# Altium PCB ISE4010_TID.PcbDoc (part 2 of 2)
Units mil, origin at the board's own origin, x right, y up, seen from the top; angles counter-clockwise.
Board outline 9000 x 8000 mil, 4 copper layers (Layer 1 - Top Layer, Layer 2 - GND, Layer 3 - PWR, Layer 4 - Bottom Layer), stack 65.6 mil thick; 159 components, 101 nets, 426 pads, 332 vias.
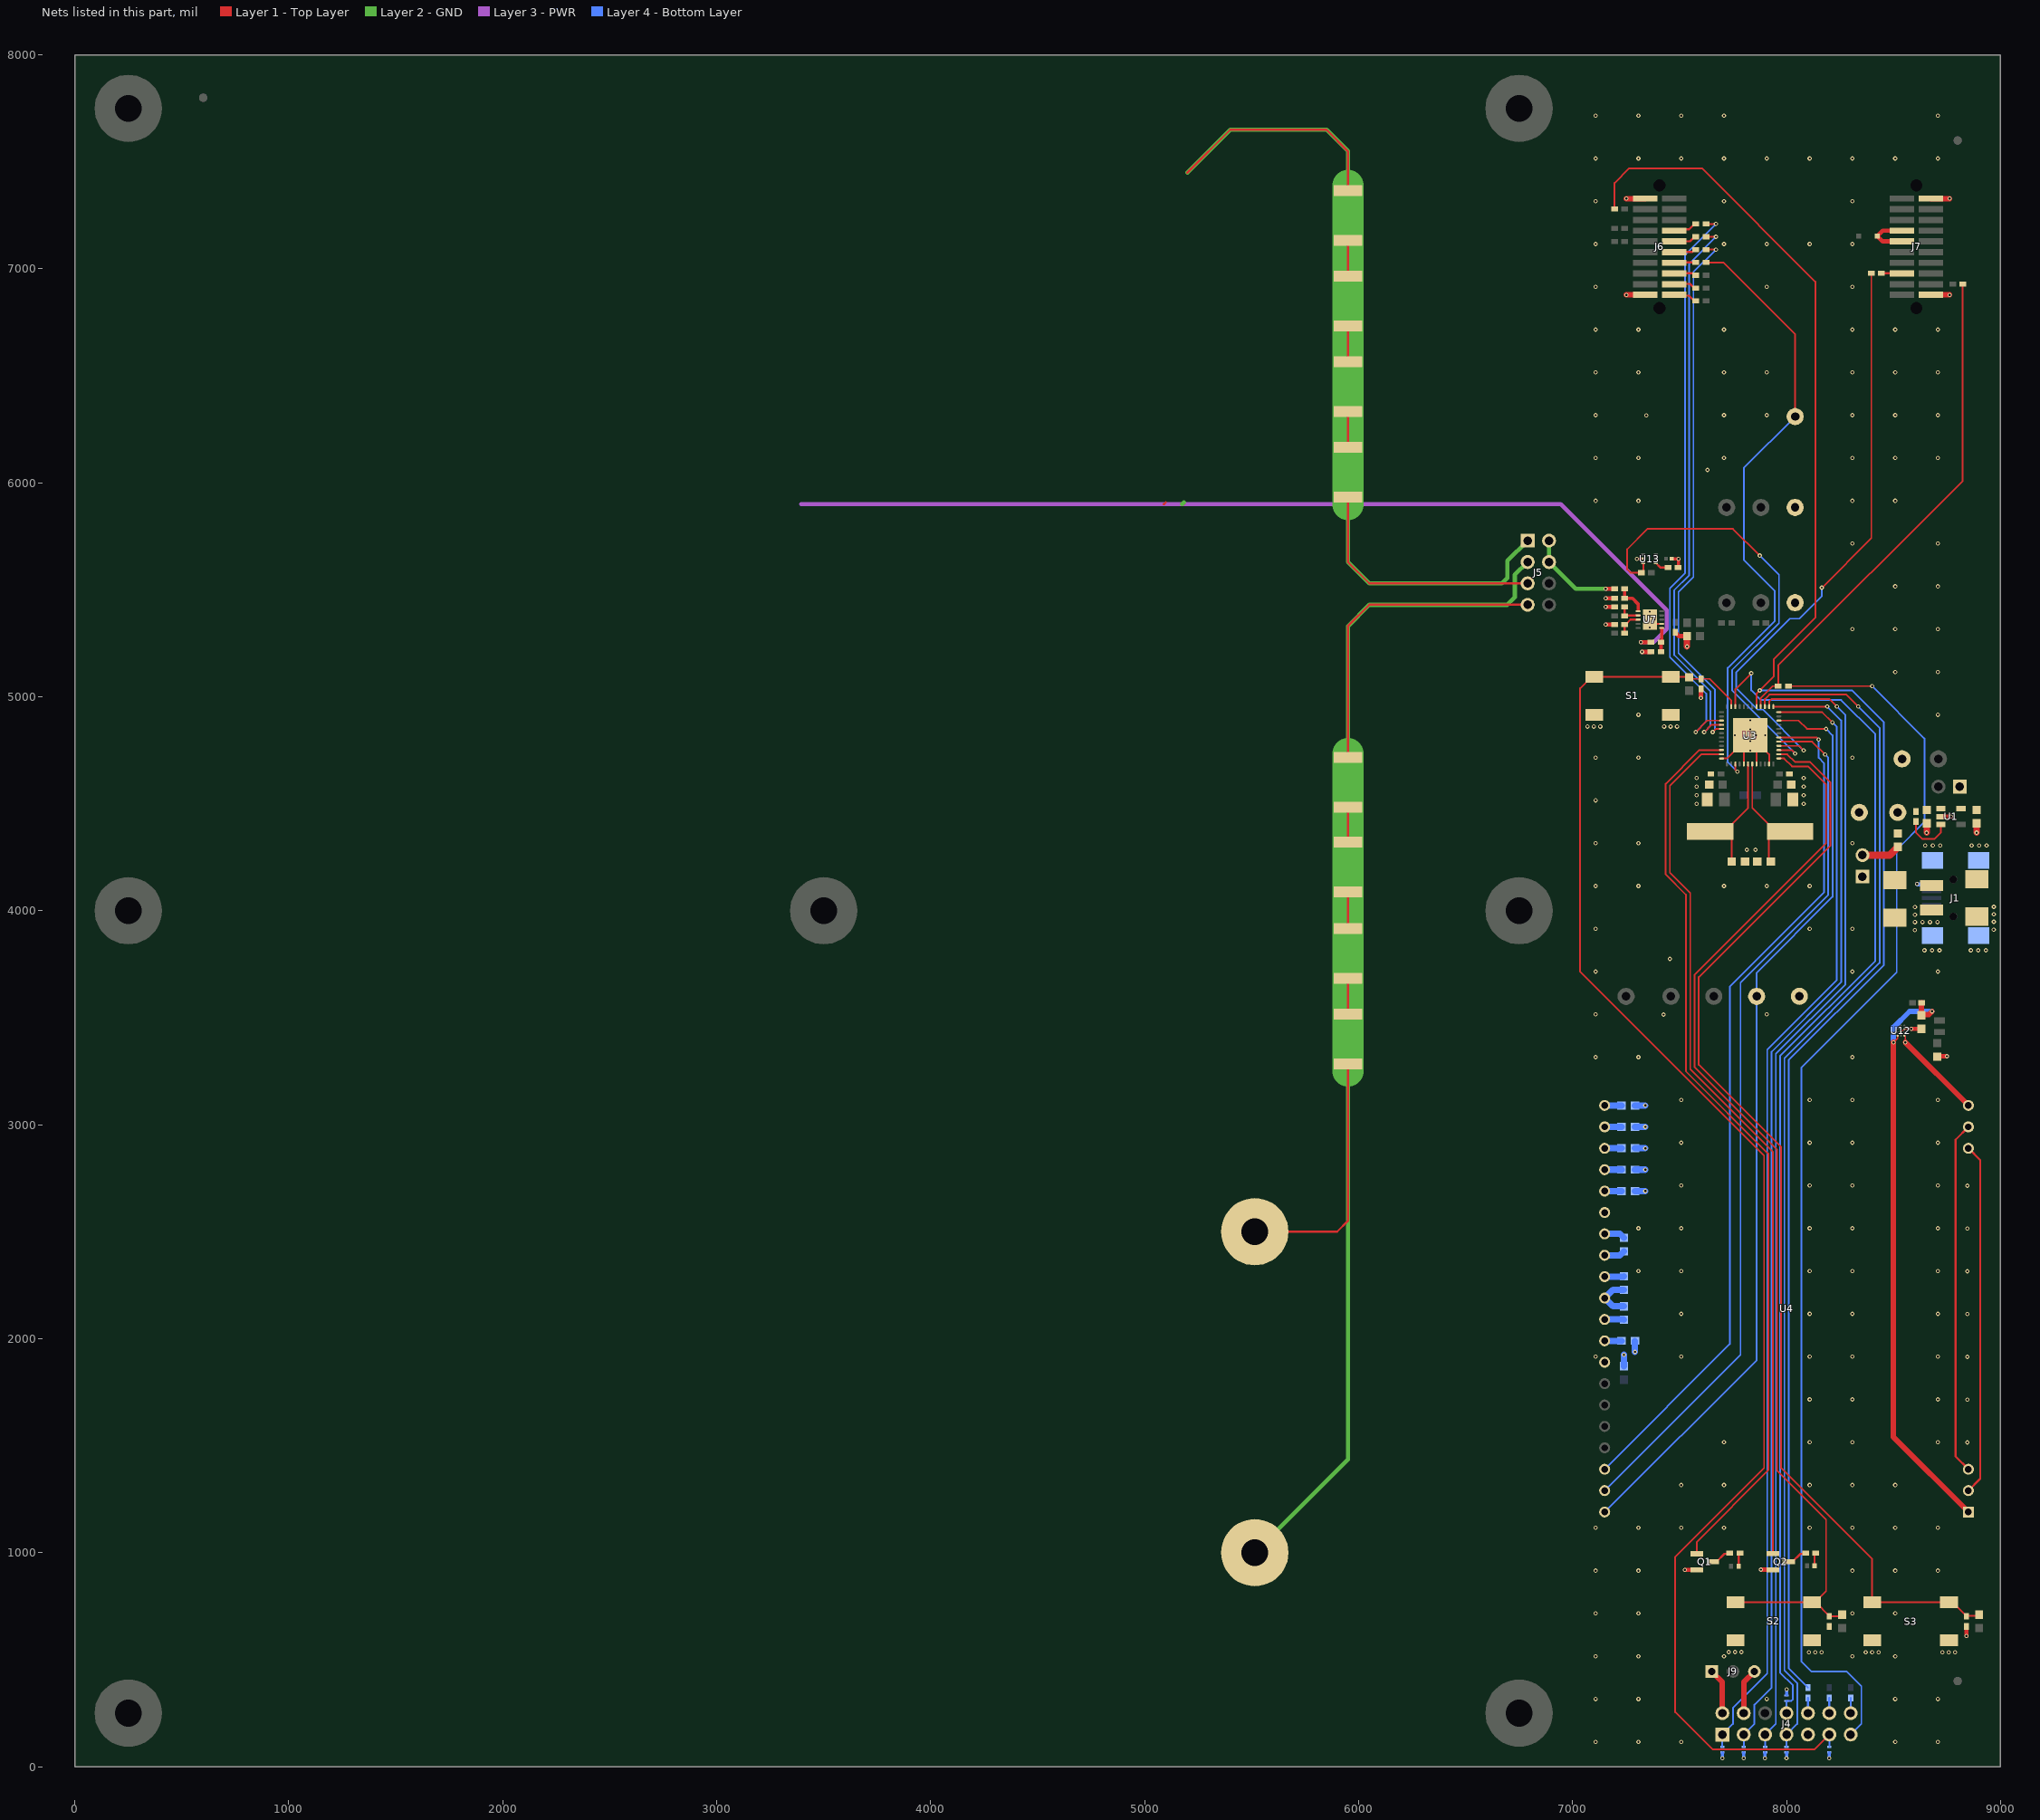
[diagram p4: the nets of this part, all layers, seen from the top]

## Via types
v1: diameter 20, hole 10, Layer 1 - Top Layer to Layer 4 - Bottom Layer, 320 vias
v2: diameter 19.68, hole 7.87, Layer 1 - Top Layer to Layer 4 - Bottom Layer, 12 vias

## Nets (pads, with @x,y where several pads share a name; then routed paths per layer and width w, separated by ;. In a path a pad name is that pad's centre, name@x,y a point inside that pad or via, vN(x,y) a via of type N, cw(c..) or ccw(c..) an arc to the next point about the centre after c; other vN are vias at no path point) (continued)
GND: C1.1 C2.2 C3.2 C4.1 C5.2 C6.2 C7.2 C9.1 C10.2 C11.1 C14.1 C15.2 C16.1 C17.2 C18.2 C19.2 C20.2 C21.2 C22.2 C23.2 C24.2 C25.2 C26.2 C27.1 C28.2 C29.1 C30.1 C34.2 C35.2 C36.2 D1.2 D6.1 J1.5 J1.6 J1.7 J1.8 J1.9 J4.9 J6.2 J6.20 J7.1 J7.19 Q1.2 Q2.2 R25.2 S1.3 S1.4 S2.3 S2.4 S3.3 S3.4 TP2.1 TP13.1 TP14.1 TP15.1 TP16.1 U1.2 U3.36 U3.41 U3.44 U3.47 U3.49 U4.26 U4.33 U5.2 U6.2 U7.7 U7.11 U8.2 U9.2 U10.2 U11.2 U12.B3 U12.C2 U13.2 | length 2260.9
  Layer 1 - Top Layer w4: U12.C2@8534.92,3432.05 U12.B3@8550.67,3447.8
  Layer 1 - Top Layer w8: U7.11@7380.82,5341.05 U7.7@7416.25,5341.05 ; U3.36@7696.14,4711.73 7721.73,4711.73 7800.47,4790.47 U3.41@7800.47,4686.14 ; U3.49@7830,4820 U3.49@7859.53,4790.47 ; U3.44@7859.53,4686.14 U3.49@7859.53,4790.47 ; U3.47@7918.58,4686.14 7918.58,4731.42 U3.49@7859.53,4790.47 ; U12.B3@8550.67,3447.8 v1(8582.8,3447.8)
  Layer 1 - Top Layer w10: v1(7300,5645) U13.2@7330.47,5645
  Layer 1 - Top Layer w15: C36.2@7462.99,5645 v1(7495,5645) 7495,5606.38 R25.2@7493.62,5605
  Layer 1 - Top Layer w20: v1(7155,5337.99) C30.1@7196.38,5337.99 ; v1(7155,5420) C29.1@7196.38,5420 ; v1(7155,5460) C2.2@7196.38,5460 ; v1(7325,5210) C3.2@7366.38,5210 ; C27.1@7480,5301.38 7497.87,5283.5 C23.2@7535,5283.5 ; v1(7525,920) Q1.2@7581.02,920 ; v1(7600,4995) C10.2@7600,5036.38 ; v1(7880,920.46) Q2.2@7936.02,920.46 ; v1(8582.8,3447.8) 8629.29,3447.8 C35.2@8629.92,3448.43 ; C34.2@8704.92,3318.43 8706.5,3320 v1(8750,3320) ; U1.2@8721.3,4440 v1(8768.54,4440) ; v1(8840.25,610.25) C17.2@8840.25,655.5
  Layer 1 - Top Layer w25: v1(7251.49,6878.51) J6.2@7339.47,6878.51 ; v1(7251.49,7328.51) J6.20@7339.47,7328.51 ; J7.1@8674.51,6878.51 v1(8762.49,6878.51) ; J7.19@8674.51,7328.51 v1(8762.49,7328.51)
  Layer 1 - Top Layer w30: v1(7535,5235) C23.2@7535,5283.5 ; v1(8655,4365) C1.1@8655,4408.5 ; v1(8888.54,4365) C4.1@8888.54,4408.5
  Layer 4 - Bottom Layer w15: v1@7700,39 U5.2@7700,64 ; v1@7800,39 U8.2@7800,64 ; v1@7900,39 U10.2@7900,64 ; v1@8000,39 U11.2@8000,64 ; U6.2@8000,336 v1@8000,361 ; v1@8200,39 U9.2@8200,64
  Layer 4 - Bottom Layer w30: C18.2@7240,1871.5 v1(7240,1925) ; v1(7291.5,1938.5) C19.2@7291.5,1990 ; C20.2@7291.5,2690 v1(7340,2690) ; C21.2@7291.5,2790 v1(7340,2790) ; C22.2@7291.5,2890 v1(7340,2890) ; C26.2@7291.5,2990 v1(7340,2990) ; C28.2@7291.5,3090 v1(7340,3090)
  other v1: 7699.75,39 7799.75,39 7899.75,39 7999.75,39 8199.75,39 7108,116 7308,116 7508,116 8508,116 8708,116 7108,316 7308,316 7908,316 8508,316 8708,316 8000.25,361 7108,516 7308,516 7708,516 8308,516 8508,516 8103.88,534.46 8133.88,534.46 8163.88,534.46 8370,535 8400,535 8430,535 8728.27,535 8758.27,535 8788.27,535 7729.75,535.88 7759.75,535.88 7789.75,535.88 7108,716 7308,716 8308,716 8508,716 7108,916 7308,916 8308,916 8508,916 8708,916 7108,1116 7308,1116 7508,1116 7708,1116 8108,1116 8308,1116 8508,1116 8708,1116 7508,1316 7708,1316 8108,1316 8308,1316 8508,1316 8845,1515 7708,1516 8108,1516 8308,1516 8708,1516 8845,1715 8108,1716 8308,1716 8708,1716 8845,1915 7108,1916 7508,1916 8108,1916 8308,1916 8708,1916 8845,2115 7508,2116 8108,2116 8308,2116 8708,2116 8845,2315 7308,2316 7508,2316 8108,2316 8308,2316 8708,2316 8845,2515 7308,2516 7508,2516 8108,2516 8308,2516 8708,2516 8845,2715 7508,2716 8108,2716 8308,2716 8708,2716 7508,2916 8108,2916 8308,2916 8708,2916 7508,3116 8108,3116 8308,3116 8708,3116 7108,3316 7308,3316 8308,3316 7425,3515 7108,3516 7908,3516 7108,3716 8308,3716 8708,3716 7455,3775 8644.68,3815 8679.68,3815 8714.68,3815 8861.22,3815 8896.22,3815 8931.22,3815 8600,3910 8968.46,3911.61 7108,3916 8108,3916 8308,3916 8600.2,3946.89 8635.2,3946.89 8670.2,3946.89 8705.2,3946.89 8968.66,3948.5 8600.2,3981.89 8968.66,3983.5 8600.2,4016.89 8968.66,4018.5 7108,4116 7308,4116 7708,4116 7908,4116 8108,4116 7815,4285 7855,4285 8648.46,4305 8683.46,4305 8718.46,4305 8865,4305 8900,4305 8935,4305 7108,4316 7308,4316 8308,4316 7580,4500 8080,4500 7108,4516 7580,4540 8080,4540 7580,4580 8080,4580 7580,4620 8080,4620 7108,4716 7308,4716 8308,4716 7069.75,4860.88 7099.75,4860.88 7129.75,4860.88 7428.02,4860.88 7458.02,4860.88 7488.02,4860.88 7308,4916 8708,4916 8508,5116 8708,5116 8308,5316 8508,5316 8708,5316 8508,5516 8708,5516 8308,5716 8708,5716 7108,5916 7308,5916 8308,5916 8508,5916 7630,6060 7108,6116 7308,6116 7708,6116 8308,6116 8508,6116 8708,6116 7345,6315 7108,6316 7708,6316 7908,6316 8308,6316 8508,6316 8708,6316 7108,6516 7308,6516 7708,6516 7908,6516 8308,6516 8508,6516 8708,6516 7108,6716 7308,6716 7708,6716 8308,6716 8508,6716 8708,6716 7108,6916 7908,6916 8308,6916 7108,7116 7708,7116 7908,7116 8108,7116 8308,7116 7108,7316 7708,7316 8308,7316 7108,7516 7308,7516 7508,7516 7708,7516 7908,7516 8108,7516 8308,7516 8508,7516 8708,7516 7108,7716 7308,7716 7508,7716 7708,7716 8708,7716
  other v2: 7830,4749.13 7830,4792.44 7759.13,4820 7802.44,4820 7857.56,4820 7900.87,4820 7830,4847.56 7830,4890.87 7361.13,5323.33 7338.5,5360.73 7383.77,5360.73 7361.13,5398.13
HFXIN: C25.1 U3.42 Y1.1 | length 583.8
  Layer 1 - Top Layer w8: Y1.1@7642.99,4370 Y1.1@7710,4370 ; Y1.1@7710,4355 Y1.1@7710,4370 ; C25.1@7743.5,4230 Y1.1@7743.5,4370 ; U3.42@7820.16,4686.14 7820.16,4480.16 Y1.1@7710,4370
HFXOUT: C24.1 U3.43 Y1.2 | length 583.8
  Layer 1 - Top Layer w8: U3.43@7839.84,4686.14 7839.84,4480.16 Y1.2@7950,4370 ; C24.1@7916.5,4230 Y1.2@7916.5,4370 ; Y1.2@7950,4355 Y1.2@7950,4370 ; Y1.2@8017.01,4370 Y1.2@7950,4370
ILED: U4.20 U12.D3 | length 450.3
  Layer 1 - Top Layer w8: U12.D3@8550.67,3416.3 8555,3411.97 v1(8555,3385)
  Layer 1 - Top Layer w25: v1(8555,3385) U4.20@8850,3090
LCD_A0: U3.6 U4.38 | length 4035.4
  Layer 1 - Top Layer w8: U3.6@7963.86,4810.16 8139.84,4810.16 v1(8150,4800)
  Layer 4 - Bottom Layer w8: U4.38@7150,1390 7735,1975 7735,3645 8175.16,4085.16 8175.16,4689.84 8150,4715 v1(8150,4800)
LED_1: Q1.1 U3.34 | length 4262.2
  Layer 1 - Top Layer w8: Q1.1@7581.02,994.8 7581.02,1051.02 7915,1385 7915,2865 7530,3250 7530,4075 7435,4170 7435,4593.28 7592.82,4751.1 U3.34@7696.14,4751.1
LED_2: Q2.1 U3.35 | length 4090.8
  Layer 1 - Top Layer w8: U3.35@7696.14,4731.42 7601.42,4731.42 7455,4585 7455,4178.28 7550,4083.28 7550,3260 7936.02,2873.98 Q2.1@7936.02,995.26
LED_CA1: U4.2 U4.18 | length 1646
  Layer 1 - Top Layer w10: U4.2@8850,1290 8905.51,1345.51 8905.51,2834.49 U4.18@8850,2890
LED_CA2: U4.3 U4.19 | length 1649.7
  Layer 1 - Top Layer w10: U4.3@8850,1390 8790,1450 8790,2930 U4.19@8850,2990
NCSB_LCD: TP9.1 U3.10 U4.40 | length 4350.9
  Layer 1 - Top Layer w8: U3.10@7963.86,4888.9 8056.1,4888.9 8095,4850 v1(8185,4850)
  Layer 4 - Bottom Layer w8: U4.40@7150,1190 7860.18,1900.18 TP9.1@7860.18,3599.88 7860.18,3710.18 8215.16,4065.16 8215.16,4819.84 v1(8185,4850)
NCSB_RF: R21.2 TP10.1 U3.39 | length 2909.4
  Layer 1 - Top Layer w8: R21.2@7623.62,7030 7705,7030 8040.18,6694.82 TP10.1@8040.18,6309.89 ; U3.39@7761.1,4686.14 7761.1,4658.9 v1(7770,4650)
  Layer 4 - Bottom Layer w8: v1(7770,4650) 7725,4695 7725,5135 7945,5355 7945,5495 7800,5640 7800,6069.71 TP10.1@8040.18,6309.89
NetC2_1: C2.1 R7.1 U7.1 | length 149.2
  Layer 1 - Top Layer w15: R7.1@7243.62,5505 C2.1@7243.62,5460 7280,5460 7306.02,5433.98 U7.1@7306.02,5403
NetC3_1: C3.1 R30.1 U7.6 | length 109.1
  Layer 1 - Top Layer w15: C3.1@7413.62,5210 R30.1@7413.62,5255 7416.25,5257.63 U7.6@7416.25,5318
NetC4_2: C4.2 J3.1 U1.5
NetC7_1: C7.1 D1.1 D6.2 J1.1 J2.1 | length 68.5
  Layer 4 - Bottom Layer w18: v1(8610,4125) 8612.01,4122.99 J1.1@8677.64,4122.99
NetC19_1: C19.1 U4.32 | length 78.5
  Layer 4 - Bottom Layer w30: U4.32@7150,1990 C19.1@7228.5,1990
NetC20_1: C20.1 U4.25 | length 78.5
  Layer 4 - Bottom Layer w30: U4.25@7150,2690 C20.1@7228.5,2690
NetC21_1: C21.1 U4.24 | length 78.5
  Layer 4 - Bottom Layer w30: U4.24@7150,2790 C21.1@7228.5,2790
NetC22_1: C22.1 U4.23 | length 78.5
  Layer 4 - Bottom Layer w30: U4.23@7150,2890 C22.1@7228.5,2890
NetC26_1: C26.1 U4.22 | length 78.5
  Layer 4 - Bottom Layer w30: U4.22@7150,2990 C26.1@7228.5,2990
NetC28_1: C28.1 U4.21 | length 78.5
  Layer 4 - Bottom Layer w30: U4.21@7150,3090 C28.1@7228.5,3090
NetC29_2: C29.2 R11.2 U7.2 | length 110.4
  Layer 1 - Top Layer w10: C29.2@7243.62,5417.99 R11.2@7243.62,5377.99 7246.05,5380.42 U7.2@7313,5380.42
NetC30_2: C30.2 R12.2 U7.3 | length 118.8
  Layer 1 - Top Layer w10: R12.2@7243.62,5297.99 C30.2@7243.62,5337.99 7248.15,5337.99 7270.89,5360.73 U7.3@7313,5360.73
NetC31_1: C31.1 U4.28 | length 97.7
  Layer 4 - Bottom Layer w30: U4.28@7150,2390 7221.5,2390 C31.1@7240,2408.5
NetC31_2: C31.2 U4.27 | length 97.7
  Layer 4 - Bottom Layer w30: U4.27@7150,2490 7221.5,2490 C31.2@7240,2471.5
NetC32_1: C32.1 U4.31 | length 90.6
  Layer 4 - Bottom Layer w30: U4.31@7150,2090 7238.5,2090 C32.1@7240,2088.5
NetC32_2: C32.2 C33.1 U4.30 | length 211.9
  Layer 4 - Bottom Layer w30: C32.2@7240,2151.5 7188.5,2151.5 U4.30@7150,2190 7188.5,2228.5 C33.1@7240,2228.5
NetC33_2: C33.2 U4.29 | length 90.6
  Layer 4 - Bottom Layer w30: U4.29@7150,2290 7238.5,2290 C33.2@7240,2291.5
NetD2_1: D2.1 R9.2 | length 62.4
  Layer 1 - Top Layer w10: D2.1@7776.14,937.4 7776.14,991.5 R9.2@7782.05,997.4
NetD3_1: D3.1 R10.2 | length 62.4
  Layer 1 - Top Layer w10: D3.1@8131.14,937.86 8131.14,991.95 R10.2@8137.05,997.86
NetD5_1: D5.1 J7.12 J7.14 | length 251
  Layer 1 - Top Layer w20: J7.12@8539.47,7128.51 8448.8,7128.51 D5.1@8424.31,7153 8449.82,7178.51 J7.14@8539.47,7178.51
NetJ4_10: J4.10 R29.2 | length 71.4
  Layer 4 - Bottom Layer w10: J4.10@8100,250 R29.2@8100,321.38
NetJ4_12: J4.12 R28.2 | length 71.4
  Layer 4 - Bottom Layer w10: J4.12@8200,250 R28.2@8200,321.38
NetJ4_13: J4.13 R8.2 | length 5864.4
  Layer 1 - Top Layer w8: R8.2@8008.62,5050 v1(8400,5050)
  Layer 4 - Bottom Layer w8: J4.13@8300,150 8350,200 8350,375 8280,445 8115,445 8070,490 8070,3268 8515,3713 8515,4285 8645,4415 8645,4805 v1(8400,5050)
NetJ4_14: J4.14 R27.2 | length 71.4
  Layer 4 - Bottom Layer w10: J4.14@8300,250 R27.2@8300,321.38
NetJ5_5: J5.5 R34.1 | length 1185.3
  Layer 1 - Top Layer w10: R34.1@5950,5933.86 5950,5630 6050,5530 J5.5@6790,5530
NetJ5_7: J5.7 R31.1 | length 1495.3
  Layer 1 - Top Layer w10: R31.1@5950,4716.14 5950,5330 6050,5430 J5.7@6790,5430
NetJ6_1: J6.1 R17.2 | length 114.9
  Layer 1 - Top Layer w10: J6.1@7475,6880 7480,6875 7544,6875 7570.49,6848.51 R17.2@7576.87,6848.51
NetJ6_3: J6.3 R19.1 | length 110.8
  Layer 1 - Top Layer w10: J6.3@7475,6930 7549,6930 7570.49,6908.51 R19.1@7576.87,6908.51
NetJ6_5: J6.5 R20.1 | length 106.6
  Layer 1 - Top Layer w10: J6.5@7475,6980 7559,6980 7570.49,6968.51 R20.1@7576.87,6968.51
NetJ6_7: J6.7 R21.1 | length 102.5
  Layer 1 - Top Layer w10: J6.7@7474.51,7028.51 7476,7030 R21.1@7576.38,7030
NetJ6_9: J6.9 R18.2 | length 106.6
  Layer 1 - Top Layer w10: J6.9@7474.51,7078.51 7558.51,7078.51 7570,7090 R18.2@7576.38,7090
NetJ6_11: J6.11 R16.2 | length 110.8
  Layer 1 - Top Layer w10: J6.11@7474.51,7128.51 7548.51,7128.51 7570,7150 R16.2@7576.38,7150
NetJ6_13: J6.13 R22.1 | length 114.9
  Layer 1 - Top Layer w10: J6.13@7474.51,7178.51 7481,7185 7545,7185 7570,7210 R22.1@7576.38,7210
NetJ7_6: J7.6 R23.1 | length 96.5
  Layer 1 - Top Layer w10: R23.1@8443.62,6980 8537.98,6980 J7.6@8539.47,6978.51
NetQ1_3: Q1.3 R9.1 | length 95.5
  Layer 1 - Top Layer w10: Q1.3@7655.83,957.4 7672.86,957.4 7710,994.54 7731.95,994.54 R9.1@7734.8,997.4
NetQ2_3: Q2.3 R10.1 | length 95.5
  Layer 1 - Top Layer w10: Q2.3@8010.83,957.86 8027.86,957.86 8065,995 8086.95,995 R10.1@8089.8,997.86
NetR1_1: R1.1 U1.3 | length 229.4
  Layer 1 - Top Layer w8: R1.1@8605,4416.38 8605,4365 8635,4335 8690,4335 8721.3,4366.3 U1.3@8721.3,4402.6
NetR25_1: R25.1 U13.4 | length 65.3
  Layer 1 - Top Layer w10: U13.4@7389.53,5625.31 7409.84,5605 R25.1@7446.38,5605
NetR31_2: R31.2 R35.1 | length 162.7
  Layer 1 - Top Layer w10: R35.1@5950,4321.14 R31.2@5950,4483.86
NetR34_2: R34.2 R38.1 | length 167.7
  Layer 1 - Top Layer w10: R34.2@5950,6166.14 R38.1@5950,6333.86
NetR35_2: R35.2 R39.1 | length 172.7
  Layer 1 - Top Layer w10: R39.1@5950,3916.14 R35.2@5950,4088.86
NetR38_2: R38.2 R42.1 | length 167.7
  Layer 1 - Top Layer w10: R38.2@5950,6566.14 R42.1@5950,6733.86
NetR39_2: R39.2 R43.1 | length 167.7
  Layer 1 - Top Layer w10: R43.1@5950,3516.14 R39.2@5950,3683.86
NetR42_2: R42.2 R46.1 | length 167.7
  Layer 1 - Top Layer w10: R42.2@5950,6966.14 R46.1@5950,7133.86
NRST: C10.1 J4.11 R4.1 S1.1 S1.2 U3.23 U9.1 | length 6995.7
  Layer 1 - Top Layer w8: U3.23@7741.42,4953.86 7741.42,4983.58 7641.38,5083.62 C10.1@7600,5083.62 7552.87,5083.62 R4.1@7545,5091.5 7542.92,5093.58 S1.2@7459.14,5093.58 S1.1@7100.87,5093.58 7088.58,5093.58 7035,5040 7035,3715 7895,2855 7895,1395 7480,980 7480,255 7655,80 8130,80 J4.11@8200,150
  Layer 4 - Bottom Layer w8: U9.1@8200,92.8 J4.11@8200,150
NRST_EM: R23.2 U3.4 | length 2787.8
  Layer 1 - Top Layer w8: U3.4@7963.86,4770.79 8059.21,4770.79 v1(8080,4750) ; v1(8165,5510) 8396.38,5741.38 R23.2@8396.38,6980
  Layer 4 - Bottom Layer w8: v1(8080,4750) 7890,4940 7865,4940 7765,5040 7765,5115 8015,5365 8060,5365 8165,5470 v1(8165,5510)
NRST_LCD: U3.5 U4.39 | length 4120.4
  Layer 1 - Top Layer w8: U3.5@7963.86,4790.47 8119.53,4790.47 v1(8180,4730)
  Layer 4 - Bottom Layer w8: U4.39@7150,1290 7785,1925 7785,3665 8195.16,4075.16 8195.16,4714.84 v1(8180,4730)
OVP: C35.1 D4.1 U4.1 U12.D1 | length 2777.2
  Layer 1 - Top Layer w8: v1(8499.92,3384.92) 8519.17,3404.17 U12.D1@8519.17,3416.3
  Layer 1 - Top Layer w25: v1(8499.92,3384.92) 8499.92,1540.08 U4.1@8850,1190 ; D4.1@8631.57,3569.92 8629.92,3568.27 C35.1@8629.92,3511.42 8633.5,3515 8665,3515 v1(8679.92,3529.92)
  Layer 4 - Bottom Layer w25: v1(8499.92,3384.92) 8499.92,3454.92 8574.92,3529.92 v1(8679.92,3529.92)
P3.4: R22.2 U3.27 | length 2745
  Layer 1 - Top Layer w8: v1(7575,4835) 7628.9,4888.9 U3.27@7696.14,4888.9 ; R22.2@7623.62,7210 v1(7670,7210)
  Layer 4 - Bottom Layer w8: v1(7575,4835) 7625,4885 7625,5015 7455,5185 7455,5506.57 7525,5576.57 7525,7065 v1(7670,7210)
P3.5: R16.1 U3.28 | length 2620.3
  Layer 1 - Top Layer w8: v1(7615,4835) 7649.21,4869.21 U3.28@7696.14,4869.21 ; R16.1@7623.62,7150 v1(7670,7150)
  Layer 4 - Bottom Layer w8: v1(7615,4835) 7645,4865 7645,5025 7475,5195 7475,5498.28 7545,5568.28 7545,7025 v1(7670,7150)
P3.6: R18.1 U3.29 | length 2495.6
  Layer 1 - Top Layer w8: R18.1@7623.62,7090 v1(7670,7090) ; v1(7655,4835) 7669.53,4849.53 U3.29@7696.14,4849.53
  Layer 4 - Bottom Layer w8: v1(7655,4835) 7665,4845 7665,5035 7495,5205 7495,5490 7565,5560 7565,6985 v1(7670,7090)
SENSOR1: R46.2 | length 1070.6
  Layer 1 - Top Layer w10: 5090,5900 5098.86,5908.86 ; 5200,7450 5400,7650 5850,7650 5950,7550 R46.2@5950,7366.14
SENSOR2: pad.@5515,2500 R43.2 | length 1189.6
  Layer 1 - Top Layer w10: pad.@5515,2500 5900,2500 5950,2550 R43.2@5950,3283.86
SHLD1: J5.2 J5.4 R7.2 | length 460.2
  Layer 1 - Top Layer w20: v1(7155,5505) R7.2@7196.38,5505 R7.2@7198.39,5505
  Layer 2 - GND w20: J5.2@6890,5730 J5.4@6890,5630 7015,5505 v1(7155,5505)
SHLD1_1: J5.1 | length 3817.9
  Layer 2 - GND w20: 5175,5900 5183.86,5908.86 ; 5200,7450 5400,7650 5850,7650 5950,7550 5950,7390 ; 5950,5898.43 5950,5630 6050,5530 6670,5530 6695,5555 6695,5635 J5.1@6790,5730
  Layer 2 - GND w145: 5950,5898.43 5950,7390
SHLD1_2: J5.3 pad.@5515,1000 | length 5536
  Layer 2 - GND w20: pad.@5515,1000 5950,1435 5950,3250 ; 5950,4735 5950,5330 6050,5430 6695,5430 6730,5465 6730,5570 J5.3@6790,5630
  Layer 2 - GND w145: 5950,3250 5950,4735
SHLD2: R30.2 | length 4530.2
  Layer 1 - Top Layer w20: v1(7320,5255) R30.2@7366.38,5255
  Layer 3 - PWR w20: 3395,5900 6945,5900 7440,5405 7440,5316.81 7378.19,5255 v1(7320,5255)
TCK: J4.7 U3.15 U11.1 | length 5636.2
  Layer 1 - Top Layer w8: U3.15@7898.9,4953.86 7898.9,4988.9 7920,5010 8280,5010 v1(8335,4955)
  Layer 4 - Bottom Layer w8: U11.1@8000,92.8 J4.7@8000,150 8050,200 8050,390 7990,450 7990,3311.28 8435,3756.28 8435,4855 v1(8335,4955)
TDI: J4.3 U3.13 U8.1 | length 5329.8
  Layer 1 - Top Layer w8: U3.13@7938.27,4953.86 8188.86,4953.86 v1(8190,4955)
  Layer 4 - Bottom Layer w8: U8.1@7800,92.8 J4.3@7800,150 7850,200 7850,290 7930,370 7930,3341.28 8255,3666.28 8255,4890 v1(8190,4955)
TDO: J4.1 U3.12 U5.1 | length 5288.2
  Layer 1 - Top Layer w8: U3.12@7963.86,4928.27 8166.73,4928.27 v1(8215,4880)
  Layer 4 - Bottom Layer w8: U5.1@7700,92.8 J4.1@7700,150 7750,200 7750,275 7910,435 7910,3351.28 8235,3676.28 8235,4860 v1(8215,4880)
TEST: J4.8 U3.22 U6.1 | length 5741.3
  Layer 1 - Top Layer w8: U3.22@7761.1,4953.86 7761.1,5036.1 v1(7835,5110)
  Layer 4 - Bottom Layer w8: v1(7835,5110) 7835,5030 7880,4985 8255,4985 8415,4825 8415,3766.28 7970,3321.28 7970,440 8030,380 8030,315 8022.2,307.2 U6.1@8000,307.2 J4.8@8000,250
TMP_ALERT: R26.1 U3.3 U13.3 | length 2186.2
  Layer 1 - Top Layer w8: U13.3@7330.47,5625.31 7330.47,5589.09 R26.1@7321.38,5580 7270,5580 7255,5595 7255,5690 7350,5785 7750,5785 v1(7875,5660) ; U3.3@7963.86,4751.1 8023.9,4751.1 v1(8040,4735)
  Layer 4 - Bottom Layer w8: v1(7875,5660) 7965,5570 7965,5345 7745,5125 7745,5030 v1(8040,4735)
TMS: J4.5 U3.14 U10.1 | length 5394.5
  Layer 1 - Top Layer w8: U3.14@7918.58,4953.86 7918.58,4978.58 7930,4990 8200,4990 v1(8235,4955)
  Layer 4 - Bottom Layer w8: U10.1@7900,92.8 J4.5@7900,150 7950,200 7950,3331.28 8275,3656.28 8275,4915 v1(8235,4955)
UART_CTS: R15.2 R29.1 U3.17 | length 8783.3
  Layer 1 - Top Layer w8: R15.2@7196.38,7280 7196.38,7401.38 7265,7470 7605,7470 8135,6940 8135,5370 7940,5175 7940,5095 7885,5040 7859.53,5014.53 U3.17@7859.53,4953.86
  Layer 4 - Bottom Layer w8: v1(7875,5030) 8305,5030 8455,4880 8455,3746.28 8010,3301.28 8010,460 8100,370 R29.1@8100,368.62
UART_RTS: R8.1 R24.1 U3.16 | length 2381
  Layer 1 - Top Layer w8: U3.16@7879.21,4953.86 7879.21,4994.21 7935,5050 R8.1@7961.38,5050 7961.38,5146.38 8823.62,6008.62 R24.1@8823.62,6928.21
USR_BTN_1: C15.1 R5.1 S2.1 S2.2 U3.1 | length 5154.4
  Layer 1 - Top Layer w8: S2.1@7760.87,768.58 S2.2@8119.13,768.58 S2.2@8133.58,768.58 ; U3.1@7963.86,4711.73 7988.58,4711.73 8025.32,4675 8100,4675 8184.75,4590.25 8184.75,4315 7570,3700.25 7570,3270 7955,2885 7955,1385 8184.75,1155.25 8184.75,819.75 S2.2@8133.58,768.58 ; R5.1@8260.25,710.61 8252.38,702.74 C15.1@8200.25,702.74 8200.25,704.75 8136.42,768.58 S2.2@8133.58,768.58
USR_BTN_2: C17.1 R6.1 S3.1 S3.2 U3.2 | length 5251.3
  Layer 1 - Top Layer w8: U3.2@7963.86,4731.42 8003.58,4731.42 8040,4695 8110,4695 8205,4600 8205,4305 7590,3690 7590,3280 7975,2895 7975,1395 8400,970 8400,781.03 S3.1@8386.67,767.7 ; S3.1@8401.12,767.7 S3.2@8759.39,767.7 8777.3,767.7 8840.25,704.75 8894.39,704.75 R6.1@8900.25,710.61
VBUS: J2.2 L1.1 | length 180.9
  Layer 1 - Top Layer w35: J2.2@8355,4260 8481.5,4260 L1.1@8520,4298.5
VBUS_FLT: C1.2 L1.2 R1.2 TP1.1 U1.1
VCC_TARGET: J4.4 J9.3 | length 215.7
  Layer 1 - Top Layer w25: J4.4@7800,250 7800,395 J9.3@7850,445
VCC_TOOL: J4.2 J9.1 | length 215.7
  Layer 1 - Top Layer w25: J9.1@7650,445 7700,395 J4.2@7700,250
pads on no net: FID1.1 FID2.1 FID3.1 FID4.1 FID5.1 FID6.1 H1.0 H3.1 H4.1 H6.1 H7.0 H9.1 H10.1 H12.1 H13.0 H14.1 J1.2 J1.3 J1.4 J1.10 J1.11 J4.6 J6.4 J6.6 J6.8 J6.10 J6.15 J6.16 J6.17 J6.19 J6.MH1 J6.MH2 J7.2 J7.4 J7.5 J7.7 J7.8 J7.9 J7.10 J7.11 J7.13 J7.15 J7.16 J7.17 J7.18 J7.20 J7.MH1 J7.MH2 LBL1.0 SH-J1.0 SH-J2.0 SH-J4.0 SH-J5.0 U1.4 U3.8 U3.9 U3.18 U3.19 U3.30 U3.33 U3.38 U3.40 U3.45 U3.46 U7.4 U7.5 U12.B2 U12.D2

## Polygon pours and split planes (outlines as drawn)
GND on Layer 1 - Top Layer "Layer 1 - Top Layer- GND" (solid, remove dead copper, pour order 6): 7000,0 9000,0 9000,8000 7000,8000
NetC7_1 on Layer 1 - Top Layer "Layer 1 - Top Layer- NetC7_1" (solid, remove dead copper, pour order 7): 8320,4205 8945,4205 8945,4070 8375,4070 8320,4125
GND on Layer 2 - GND "Layer 2 - GND- GND" (solid, remove dead copper, pour order 8): 7000,0 9000,0 9000,8000 7000,8000
GND on Layer 4 - Bottom Layer "Layer 4 - Bottom Layer- GND" (solid, remove dead copper, pour order 10): 7000,0 9000,0 9000,8000 7000,8000 7000,0
3V3 on Layer 3 - PWR "Layer 3 - PWR- 3V3" (solid, remove dead copper, pour order 9): 7000,0 9000,0 9000,8000 7000,8000

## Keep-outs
Keep-Out Layer:
  text ".Layer_Name" at 577,-808.49 h60

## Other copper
Layer 1 - Top Layer:
  region net SENSOR1: 4828.5,7474.8 4828.5,4325.2 5222.2,4325.2 5222.2,7474.8
  rectangle net SENSOR1: 497.8,4325.2 4942.68,4718.9
  rectangle net SENSOR1: 497.8,7081.1 4934.8,7474.8
  region net SENSOR1: 497.8,7474.8 497.8,4325.2 891.5,4325.2 891.5,7474.8
  pour cut-out: 8000,4655 8095,4655 8095,4665 8000,4665
  pour cut-out: 8200,4765 8245,4765 8245,4850 8360,4965 8360,5030 8200,5030
  pour cut-out: 8350,7125 8400,7125 8400,7185 8350,7185
  pour cut-out: 7650,6925 7775,6925 7775,6932.6 7696.98,7010.63 7654.37,7010.63
  pour cut-out: 7725,5800 7775,5800 7775,5825 7725,5825
  pour cut-out: 7275,5275 7450,5275 7450,5427.66 7275,5427.66
  pour cut-out: 7625,4975 7625,5050 7750,5050 7750,4975
  pour cut-out: 7550,4655 7675,4655 7675,4725 7550,4725
  pour cut-out: 8800,2825 8900,2825 8900,2950 8800,2950
  pour cut-out: 8800,1150 8900,1150 8900,1450 8800,1450
  pour cut-out: 7650,100 8350,100 8350,300 7650,300
  region net GND: 7715,620 7715,515 7805,515 7805,620
  region net GND: 8075,620 8075,513.58 8179.13,513.58 8179.13,620
  region net GND: 8713.52,619.12 8713.52,514.12 8803.52,514.12 8803.52,619.12
  region net GND: 7055,4945 7055,4840 7145,4840 7145,4945
  region net GND: 7413.27,4945 7413.27,4840 7503.27,4840 7503.27,4945
  pour cut-out: 7680,4671.69 7980,4671.69 7980,4970 7680,4970
  region net GND: 8440,4005 8470,4035 8735,4035 8735,3895 8720,3880 8440,3880
  region net VBUS_FLT: 8545,4340 8545,4400 8590,4445 8670,4445 8690,4465 8745,4465 8745,4500 8720,4525 8485,4525 8445,4485 8445,4385 8490,4340
  region net NetC4_2: 8775,4483 8775,4615 8860,4615 8925,4550 8925,4455 8803,4455
  region net GND: 8355.25,619.12 8355.25,514.12 8445.25,514.12 8445.25,619.12
  region net 3V3: 7675,4655 7675,4485 7775,4485 7775,4595 7727,4643 7727,4698 7718,4698
  region net GND: 7665,4485 7565,4485 7565,4655 7665,4655
  region net GND: 7995,4485 8095,4485 8095,4655 7995,4655
  region net AVCC: 7985,4655 7985,4485 7885,4485 7885,4595 7933,4643 7933,4698 7942,4698
  region net GND: 7785,4205 7885,4205 7885,4275 7860,4300 7810,4300 7785,4275
  text ".Layer_Name" at 577,-808.49 h60
Layer 3 - PWR:
  region net SHLD2: 2440,5400 3440,5400 3440,6400 2440,6400
  text ".Layer_Name" at 577,-808.49 h60
Layer 2 - GND:
  region net SHLD1_1: 4828.5,7474.8 4828.5,4325.2 5222.2,4325.2 5222.2,7474.8
  rectangle net SHLD1_1: 497.8,4325.2 4942.68,4718.9
  rectangle net SHLD1_1: 497.8,7081.1 4934.8,7474.8
  region net SHLD1_1: 497.8,7474.8 497.8,4325.2 891.5,4325.2 891.5,7474.8
  text ".Layer_Name" at 577,-808.49 h60
Layer 4 - Bottom Layer:
  pour cut-out: 8310,4200 8310,4310 8400,4310 8400,4200
  pour cut-out: 8650,4525 8875,4525 8875,4625 8725,4775 8650,4775
  pour cut-out: 8600,4425 8600,4525 8475,4525 8475,4425
  pour cut-out: 7650,3650 7700,3650 7900,3850 7700,3850 7650,3800
  pour cut-out: 7650,100 8375,100 8375,300 7650,300
  region net CIN2: 2440,5400 3440,5400 3440,6400 2440,6400
  region net GND: 8575,4020 8575,3865 8640,3800 8735,3800 8735,4007 8628,4007 8615,4020
  region net GND: 8734.68,4190 8734.68,4320 8629.68,4320 8629.68,4190
  region net GND: 8951.22,4190 8951.22,4320 8846.22,4320 8846.22,4190
  region net GND: 8845,3930 8845,3800 8950,3800 8950,3930
  region net 3V3: 7740,4485 7790,4485 7820,4515 7820,4565 7790,4595 7740,4595
  region net AVCC: 7920,4485 7870,4485 7840,4515 7840,4565 7870,4595 7920,4595
  text ".Layer_Name" at 577,-808.49 h60

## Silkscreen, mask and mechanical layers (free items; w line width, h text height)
Top Overlay:
  lines w10: 5224.41,3349.61 5224.41,3349.61 ; 5224.41,3349.61 5224.41,3349.61 ; 500,200 500,200 ; 500,3349.61 500,3349.61
  lines w15: 7140,6728.21 8880,6728.21 8880,7468.21 7140,7468.21 7140,6728.21
  lines w20: 500,200 500,3349.61 5224.41,3349.61 5224.41,2750 5715,2750 5715,2250 5224.41,2250 5224.41,200 500,200 ; 895,595 895,2955 4830,2955 4830,595 895,595
  lines w25: 7000,0 7000,8000
  text "ISE4010 / TIDA-00220" at 7740,7605 h75
  text "Sensor 1" at 2700,7600 h150
  text "Rev. E2" at 7740,7535 h75
  text "EM Connector" at 7780,7368.21 h75
  text "for Wireless" at 7780,7308.21 h75
  text "Connectivity" at 7780,7248.21 h75
  text "nCSB_RF" at 8090,6395 h75 r90
  text "A1_RX" at 7770,5965 h75 r90
  text "A1_TX" at 7930,5965 h75 r90
  text "GND" at 8090,5965 h75 r90
  text "Shield1" at 6455,5705 h75
  text "Shield2" at 6455,5605 h75
  text "B0_SDA" at 7770,5560 h75 r90
  text "B0_SCL" at 7930,5560 h75 r90
  text "GND" at 8090,5560 h75 r90
  text "Sensor1" at 6455,5505 h75
  text "Sensor2" at 6455,5405 h75
  text "RST" at 7155,5140 h75 r90
  text "For evaluation only; not FCC approved for resale" at 8965,5000 h75 r90
  text "GND" at 8585,4785 h75 r90
  text "3V3" at 8765,4785 h75 r90
  text "Remove if" at 8830,4655 h45 r90
  text "using VCC_TOOL" at 8875,4655 h45 r90
  text "GND" at 8395,4535 h75 r90
  text "VBUS" at 8560,4530 h45 r90
  text "FLT" at 8605,4530 h45 r90
  text "A0_SIMO" at 7300.18,3679.88 h75 r90
  text "A0_SOMI" at 7510,3680 h75 r90
  text "A0_SCLK" at 7710,3680 h75 r90
  text "nCSB_LCD" at 7910.18,3679.88 h75 r90
  text "GND" at 8120,3680 h75 r90
  text "Sensor 2" at 2700,3500 h150
  text "USER" at 8490.25,829.12 h75 r90
  text "BTN_2" at 8550.25,829.12 h75 r90
  text "USER" at 7610.25,574.12 h75 r90
  text "BTN_1" at 7670.25,574.12 h75 r90
  text "VCC_TOOL" at 7520,528 h40
  text "VCC_TARGET" at 7810,525 h40
  text ".Layer_Name" at 577,-808.49 h60
Bottom Overlay:
  lines w10: 5224.41,3349.61 5224.41,3349.61 ; 5224.41,3349.61 5224.41,3349.61 ; 500,3349.61 500,3349.61
  lines w20: 500,200 500,3349.61 5224.41,3349.61 5224.41,1250 5715,1250 5715,750 5224.41,750 5224.41,200 500,200 ; 895,595 4830,595 4830,2955 895,2955 895,595
  text ".Layer_Name" at 577,-808.49 h60
Top Paste:
  text ".Layer_Name" at 577,-808.49 h60
Bottom Paste:
  text ".Layer_Name" at 577,-808.49 h60
Top Solder:
  region: 530,230 5195,230 5195,2280 5680,2280 5680,2720 5195,2720 5195,3320 530,3320 530,560 870,560 870,2990 4860,2990 4860,560 530,560
  text ".Layer_Name" at 577,-808.49 h60
  text ".Layer_Name" at 577,-808.49 h60
Bottom Solder:
  region: 530,3320 5195,3320 5195,1225 5685,1225 5685,785 5190,785 5190,230 530,230 530,2990 875,2990 875,560 4860,560 4860,2990 530,2990
  text ".Layer_Name" at 577,-808.49 h60
Drill Guide:
  text ".Layer_Name" at 577,-808.49 h60
M1 Board Outline:
  the board outline again, w7
  text ".Layer_Name" at 577,-808.49 h60
M2 Board Dimensions:
  rectangle: 125,-360.5 500,-235.5
  rectangle: 0,-235.5 125,-110.5
  lines w7: 0,-235.5 1000,-235.5 ; 0,-110.5 0,-360.5 1000,-360.5 1000,-110.5 ; 125,-360.5 125,-110.5 ; 250,-360.5 250,-110.5 ; 500,-360.5 500,-110.5 ; 750,-360.5 750,-110.5
  text ".Layer_Name" at 577,-808.49 h60
M3 3D STEP Top:
  text ".Layer_Name" at 577,-808.49 h60
M4 3D STEP Bottom:
  text ".Layer_Name" at 577,-808.49 h60
M5 Assembly Top:
  lines w10: -292,-880.17 6308,-880.17 ; -292,-676.83 6310,-676.83 ; -292,-473.5 -292,-1083.5 3713,-1083.5 6310,-1083.5 6310,-473.5 -291.5,-473.5 -291.5,-1083.5 1284,-1083.5 ; 2173,-1083.5 2173,-473.5 ; 3440,-676.83 3440,-473.5 ; 4280,-676.83 4280,-473.5 ; 4902,-1090 4902,-887.17
  text "COMPONENTS MARKED 'DNP' SHOULD NOT BE POPULATED." at 1153.5,-268.5 h60
  text "ASSEMBLY VARIANT:" at 1153,-384 h60
  text ".VariantName" at 2189,-384 h60
  text "PCB VIEWED FROM TOP SIDE" at -228.5,-605.67 h60
  text "BOARD #:" at 2248,-605.67 h60
  text ".PRJ_Number" at 2793.5,-605.67 h60
  text "REV:" at 3638,-605.67 h60
  text ".PCB_Rev" at 3929.5,-605.67 h60
  text "SVN REV:" at 4476,-605.67 h60
  text ".VersionControl_RevNumber" at 4982,-605.67 h60
  text "IGNORE ->" at -228.5,-808.49 h60
  text "PLOT NAME =" at -228.5,-1014.34 h60
  text ".plot_File_Name" at 577,-1014.34 h60
  text "GENERATED    :" at 2250,-1014.34 h60
  text ".Print_Date" at 3119.5,-1014.34 h60
  text ".Print_Time" at 3848.5,-1014.34 h60
  text "TEXAS INSTRUMENTS" at 5113,-1014.34 h60
M6 Assembly Bottom:
  lines w10: -292.5,-677.33 6309.5,-677.33 ; -290.5,-880.67 6309.5,-880.67 ; 1115.5,-1090.5 1115.5,-887.67 ; 1737.5,-677.33 1737.5,-474 ; 2577.5,-677.33 2577.5,-474 ; 3844.5,-1084 3844.5,-474 ; 4733.5,-1084 6309,-1084 6309,-474 -292.5,-474 -292.5,-1084 2304.5,-1084 6309.5,-1084 6309.5,-474
  text "COMPONENTS MARKED 'DNP' SHOULD NOT BE POPULATED." at 6102,-268 h60
  text ".VariantName" at 5058,-384 h60
  text "ASSEMBLY VARIANT:" at 6097,-384 h60
  text ".VersionControl_RevNumber" at 1035.5,-606.17 h60
  text "SVN REV:" at 1541.5,-606.17 h60
  text ".PCB_Rev" at 2088,-606.17 h60
  text "REV:" at 2379.5,-606.17 h60
  text ".PRJ_Number" at 3224,-606.17 h60
  text "BOARD #:" at 3769.5,-606.17 h60
  text "PCB VIEWED FROM BOTTOM SIDE" at 6246,-606.17 h60
  text "IGNORE ->" at 2547.85,-808.49 h60
  text "TEXAS INSTRUMENTS" at 904.5,-1014.84 h60
  text ".Print_Time" at 2169,-1014.84 h60
  text ".Print_Date" at 2898,-1014.84 h60
  text "GENERATED    :" at 3767.5,-1014.84 h60
  text ".plot_File_Name" at 5440.5,-1014.84 h60
  text "PLOT NAME =" at 6246,-1014.84 h60
M9 Title Sheet:
  drawing of 57 lines, arcs and shapes, not listed
  text "1" at 739.84,8086.5 h70
  text "2" at 3235.5,8086.5 h70
  text "3" at 5724.84,8086.5 h70
  text "4" at 8231.51,8086.5 h70
  text "5" at 10730.5,8086.5 h70
  text "6" at 13235.5,8086.5 h70
  text "A" at -416.5,6943.5 h70
  text "A" at 14383.5,6943.5 h70
  text "B" at -416.5,4563.5 h70
  text "B" at 14383.5,4563.5 h70
  text "C" at -416.5,2188.5 h70
  text "C" at 14383.5,2188.5 h70
  text "PROJECT TITLE:" at 11343.5,327.5 h45
  text ".PRJ_Title" at 11393.5,194.17 h70
  text "DESIGNED FOR:" at 11343.5,26.5 h45
  text ".PRJ_Customer" at 11393.5,-113.5 h70
  text "D" at -416.5,-181.5 h70
  text "D" at 14383.5,-181.5 h70
  text "FILE NAME:" at 11343.5,-273.5 h45
  text ".PCB_File_Name_No_Path" at 11393.5,-393.5 h70
  text "Texas Instruments (TI) and/or its licensors do not warrant the accuracy or completeness of this specification" at 6374,-555.34 h45
  text "ENGINEER:" at 11343.5,-563.5 h45
  text "LAYOUT BY:" at 12848.5,-563.5 h45
  text "or any information contained therein. TI and/or its licensors do not warrant that this design will meet" at 6329.01,-668 h45
  text ".PRJ_Engineer" at 11393.5,-718.49 h70
  text ".PCB_Layout" at 12899,-718.49 h70
  text "the specifications, will be suitable for your application or fit for any particular purpose, or will operate in" at 6329.01,-780.67 h45
  text ".Layer_Name" at 577,-808.49 h60
  text "ALTIUM DESIGNER VERSION:" at 12848.5,-873.5 h45
  text "an implementation. TI and/or its licensors do not warrant that the design is production worthy. You should" at 6329.01,-893.33 h45
  text "completely validate and test your design implementation to confirm the system functionality for your application." at 6374,-1006 h45
  text ".print_Scale" at 11393.5,-1006.83 h70
  text ".Application_BuildNumber" at 12899,-1006.83 h70
  text "1" at 739.84,-1213.5 h70
  text "2" at 3235.5,-1213.5 h70
  text "3" at 5724.84,-1213.5 h70
  text "4" at 8231.51,-1213.5 h70
  text "5" at 10730.5,-1213.5 h70
  text "6" at 13235.5,-1213.5 h70
M10 Fab Notes:
  drawing of 185 lines, arcs and shapes, not listed
  text "DESIGN INFORMATION" at 12381.02,5960 h60
  text "MIN. TRACK WIDTH:" at 11736.46,5780 h60
  text "8" at 12832.7,5780 h60
  text "MIL" at 12987.46,5780 h60
  text "5" at 12835,5650 h60
  text "MIN. CLEARANCE:" at 11736.46,5648 h60
  text "MIL" at 12987.46,5648 h60
  text "MIN. VIA PAD SIZE:" at 11736.46,5516 h60
  text "20" at 12802.71,5516 h60
  text "MIL" at 12987.46,5516 h60
  text "0.05mm (2MIL)" at 12431.46,5374.29 h60
  text "MINIMUM ANNULAR RING" at 11407.23,5370 h60
  text "EXTERNAL" at 13139.46,5370 h60
  text "PER" at 11607.23,5252 h60
  text "IPC-D-275 CLASS 2 LEVEL C" at 11827.23,5252 h60
  text "MIL, HOLES" at 13315.46,5139.71 h60
  text "+/-" at 12923,5139 h60
  text "+/-" at 13777,5139 h60
  text "REGISTRATION TOLERANCES:" at 11407.23,5134 h60
  text "METAL" at 12607,5134 h60
  text "5" at 13183.2,5134 h60
  text "3" at 14016.2,5134 h60
  text "MIL" at 14132.46,5134 h60
  text "MATERIAL:" at 11332.46,4924.54 h60
  text "FR-4 High Tg" at 12318.9,4784.21 h60
  text "FR-408" at 11753.46,4775.64 h60
  text "X" at 12165.46,4775.64 h60
  text "OTHER" at 13241.46,4775.64 h60
  text "62 MIL (1.6mm) +/-10%" at 12073.56,4612.92 h60
  text "THICKNESS:" at 11407.23,4608.64 h60
  text "X" at 11945.4,4608.64 h60
  text "OTHER" at 13358.46,4608.64 h60
  text "TOLERANCE:" at 11407.23,4450.64 h60
  text "X" at 12246.53,4450.64 h60
  text "ANSI IPC-6012 TYPE 3 CLASS 2" at 12433.48,4450.64 h60
  text "OTHER +/-" at 12433.46,4294.64 h60
  text "BOW & TWIST:" at 11407.23,4137.64 h60
  text "X" at 12246.53,4137.64 h60
  text "ANSI IPC-6012 TYPE 3 CLASS 2" at 12433.48,4137.64 h60
  text "OTHER +/-" at 12433.46,3979.13 h60
  text "DRILLING:" at 11332.46,3840.64 h60
  text "REFERENCE:" at 11407.23,3723.64 h60
  text "X" at 12055.46,3723.64 h60
  text "AS SHOWN" at 12242.46,3723.64 h60
  text "X" at 12956.46,3723.64 h60
  text "NC_DRILL FILES" at 13093.46,3723.64 h60
  text "PTH MIN COPPER THICKNESS:" at 11407.23,3565.64 h60
  text "X" at 12757.46,3565.64 h60
  text "1MIL" at 12894.46,3565.64 h60
  text "OTHER" at 13391.46,3565.64 h60
  text "BOARD FINISH:" at 11332.46,3406.64 h60
  text "SILKSCREEN:" at 11487.68,3288.64 h60
  text "X" at 12436.46,3288.64 h60
  text "TOP" at 12562.46,3288.64 h60
  text "X" at 12946.46,3288.64 h60
  text "BOTTOM" at 13073.46,3288.64 h60
  text "SILKSCREEN COLOR:" at 11487.68,3121.64 h60
  text "X" at 12435.42,3121.64 h60
  text "WHITE" at 12562.46,3121.64 h60
  text "OTHER" at 13073.46,3121.64 h60
  text "SOLDER RESIST COLOR:" at 11487.68,2951.64 h60
  text "X" at 12055.42,2792.44 h60
  text "GREEN" at 12182.46,2792.44 h60
  text "BLUE" at 12773.46,2792.44 h60
  text "OTHER" at 13311.46,2792.44 h60
  text "IMMERSION GOLD (ENIG)" at 12393.46,2603.92 h60
  text "ENEPIG" at 13731,2600.64 h60
  text "SURFACE FINISH:" at 11332.46,2599.64 h60
  text "X" at 12206.51,2599.64 h60
  text "IMM. TIN/SILVER OR EQUIV" at 11662,2442.64 h60
  text "OTHER" at 13093.46,2442.64 h60
  text "ARRAY/PANEL:" at 11332.46,2263.64 h60
  text "CUT AND TRIM PER MECH LAYER 1" at 12393.46,2259.35 h60
  text "N.C. ROUTE" at 12393.46,2107.64 h60
  text "X" at 13072.46,2107.64 h60
  text "V. SCORE" at 13259.46,2107.64 h60
  text "CERTIFICATION:" at 11332.46,1970.64 h60
  text "MATERIALS AND WORKMANSHIP FOR ALL PCBS" at 12057.46,1970.64 h60
  text "TO MEET OR EXCEED THE REQUIREMENTS OF:" at 12057.46,1872.64 h60
  text "X" at 11683.96,1736.13 h60
  text "ANSI IPC-A-600F CLASS ->" at 11822.96,1736.13 h60
  text "X" at 13462.02,1736.13 h60
  text "2" at 13580.96,1736.14 h60
  text "1" at 13265.96,1734.64 h60
  text "3" at 13934.96,1734.64 h60
  text "X" at 11686.02,1576.64 h60
  text "UL 94V-0" at 11822.96,1576.64 h60
  text "X" at 12498.02,1576.64 h60
  text "RoHS" at 12634.96,1576.64 h60
  text "OTHER" at 13279.36,1576.64 h60
  text "PER ORDER" at 13676.42,1576.64 h60
  text "ADDITIONAL REQUIREMENTS:" at 11332.46,1435.64 h60
  text "MICROSECTION:" at 11407.23,1320.64 h60
  text "YES" at 12312.96,1320.64 h60
  text "REQUIRED" at 13174.46,1164.49 h60
  text "BARE BOARD ELEC. TEST:" at 11407.23,1161.64 h60
  text "NONE" at 12712.96,1161.64 h60
  text "X" at 13047.46,1161.64 h60
  text "PER ORDER" at 13766.46,1161.64 h60
  text "MANUFACTURER'S UL:" at 11407.23,1004.64 h60
  text "RAIL" at 12572.96,1000.35 h60
  text "METAL" at 13064.77,1000.35 h60
  text "X" at 13440,1000 h60
  text "SILK" at 13576.46,1000.35 h60
  text ".Layer_Name" at 577,-808.49 h60
M11 Gerber Information:
  lines w10: -292,-880.17 6308,-880.17 ; -292,-676.83 6310,-676.83 ; -292,-473.5 -292,-1083.5 3713,-1083.5 6310,-1083.5 6310,-473.5 -291.5,-473.5 -291.5,-1083.5 1284,-1083.5 ; 2173,-1083.5 2173,-473.5 ; 3440,-676.83 3440,-473.5 ; 4280,-676.83 4280,-473.5 ; 4902,-1090 4902,-887.17
  text "ALL ARTWORK VIEWED FROM TOP SIDE" at -228.5,-605.67 h60
  text "BOARD #:" at 2248,-605.67 h60
  text ".PRJ_Number" at 2793.5,-605.67 h60
  text "REV:" at 3638,-605.67 h60
  text ".PCB_Rev" at 3929.5,-605.67 h60
  text "SVN REV:" at 4476,-605.67 h60
  text ".VersionControl_RevNumber" at 4982,-605.67 h60
  text "LAYER NAME =" at -228.5,-808.49 h60
  text "PLOT NAME =" at -228.5,-1014.34 h60
  text ".plot_File_Name" at 577,-1014.34 h60
  text "GENERATED    :" at 2250,-1014.34 h60
  text ".Print_Date" at 3119.5,-1014.34 h60
  text ".Print_Time" at 3848.5,-1014.34 h60
  text "TEXAS INSTRUMENTS" at 5113,-1014.34 h60
M12 Stackup:
  lines w4: 9570,7844.5 14248.5,7844.5 ; 9570,7918.2 14248.5,7918.2 ; 9510,7364 ccw(c9534,7364) 9534,7340 14284.5,7340 ccw(c14284.5,7364) 14308.5,7364 14308.5,7986 ccw(c14284.5,7986) 14284.5,8010 9534,8010 ccw(c9534,7986) 9510,7986 9510,7364
  text "Layer Stack Up Detail for: ISE4010 E1_PCB.PcbDoc" at 9570,7938.1 h35
  text "Layer" at 9570,7890.7 h17
  text "Gerber" at 10537.58,7890.7 h17
  text "Copper" at 11172.21,7890.7 h17
  text "Dielectric" at 11834.6,7890.7 h17
  text "Dielectric" at 12508.88,7890.7 h17
  text "Dielectric" at 13256.53,7890.7 h17
  text "Dielectric" at 13930.81,7890.7 h17
  text "Name" at 9570,7856.7 h17
  text "Document" at 10537.58,7856.7 h17
  text "Thickness" at 11172.21,7856.7 h17
  text "Height" at 11834.6,7856.7 h17
  text "Material" at 12508.88,7856.7 h17
  text "Constant" at 13256.53,7856.7 h17
  text "Type" at 13930.81,7856.7 h17
  text "Top Solder Mask" at 9570,7807.6 h24
  text "(.GTS)" at 10537.58,7807.6 h24
  text "0.4mil" at 11834.6,7807.6 h24
  text "Solder Resist" at 12508.88,7807.6 h24
  text "3.50" at 13256.53,7807.6 h24
  text "Layer 1 - Top Layer" at 9570,7737.81 h24
  text "(.GTL)" at 10537.58,7737.81 h24
  text "1.4mil" at 11172.21,7737.81 h24
  text "10mil" at 11834.6,7702.92 h24
  text "370HR" at 12508.88,7702.92 h24
  text "4.80" at 13256.53,7702.92 h24
  text "Core" at 13930.81,7702.92 h24
  text "Layer 2 - GND" at 9570,7668.02 h24
  text "(.G1)" at 10537.58,7668.02 h24
  text "1.4mil" at 11172.21,7668.02 h24
  text "40mil" at 11834.6,7633.13 h24
  text "370HR" at 12508.88,7633.13 h24
  text "4.80" at 13256.53,7633.13 h24
  text "PrePreg" at 13930.81,7633.13 h24
  text "Layer 3 - PWR" at 9570,7598.23 h24
  text "(.G2)" at 10537.58,7598.23 h24
  text "1.4mil" at 11172.21,7598.23 h24
  text "10mil" at 11834.6,7563.33 h24
  text "370HR" at 12508.88,7563.33 h24
  text "4.80" at 13256.53,7563.33 h24
  text "Core" at 13930.81,7563.33 h24
  text "Layer 4 - Bottom Layer" at 9570,7528.44 h24
  text "(.GBL)" at 10537.58,7528.44 h24
  text "1.4mil" at 11172.21,7528.44 h24
  text "Bottom Solder Mask" at 9570,7458.65 h24
  text "(.GBS)" at 10537.58,7458.65 h24
  text "0.4mil" at 11834.6,7458.65 h24
  text "Solder Resist" at 12508.88,7458.65 h24
  text "3.50" at 13256.53,7458.65 h24
  text ".Layer_Name" at 577,-808.49 h60
M13 Component Bodies Top:
  text ".Layer_Name" at 577,-808.49 h60
M14 Component Bodies Bottom:
  text ".Layer_Name" at 577,-808.49 h60
M15 Courtyards Top:
  text ".Layer_Name" at 577,-808.49 h60
M16 Courtyards Bottom:
  text ".Layer_Name" at 577,-808.49 h60
Drill Drawing:
  text ".legend" at 9230,6095 h60
  text "Drill Table" at 9255,5910 h60
  text ".Layer_Name" at 577,-808.49 h60

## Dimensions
0,0 to 0,8000 on M2 Board Dimensions
0,0 to 9000,0 on M2 Board Dimensions
0,-360.5 to 1000,-360.5 on M2 Board Dimensions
